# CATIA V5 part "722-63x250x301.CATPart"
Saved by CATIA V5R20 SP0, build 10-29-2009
Part number: 722-63x250x301
Definition: NONE
Nomenclature: 722-63x250x301
Source: Unknown
Description: 722-63x250x301
Bounding box of the stored display mesh (mm): x -31.5 to 31.5, y -31.5 to 31.5, z -232 to 69
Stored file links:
  C:\Users\Utente\Desktop\IO LAVORO\3D X SITO CF\X SITO\722\722-63x250x301.CATPart
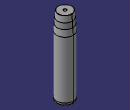
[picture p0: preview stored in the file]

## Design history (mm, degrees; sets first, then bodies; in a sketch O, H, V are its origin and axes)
Body1 "722-63x250x301" (main body)
  Solid1: solid without history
